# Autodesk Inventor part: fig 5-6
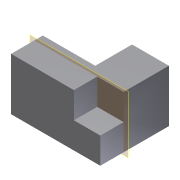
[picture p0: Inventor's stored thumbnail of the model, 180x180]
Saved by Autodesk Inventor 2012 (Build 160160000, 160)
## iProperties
Created: 2010-02
Part Number: fig 5-6
Document SubType Name: Modeling
Designer: CADSoft
Density: 1 g/cm^3
Material: Default
Author: CADSoft
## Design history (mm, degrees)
sketch "Sketch1"
  geometry: L1 (0, 26.227)-(0, 12.145); L2 (0, 12.145)-(-20.026, 12.145); L3 (-20.026, 12.145)-(-20.026, 0); L4 (-20.026, 0)-(14.083, 0); L5 (14.083, 0)-(14.083, 26.227); L6 (14.083, 26.227)-(0, 26.227); 1 further point
  constraints: 12 end point
extrude "Extrusion1" new body sketch "Sketch1" distance "d0" = 20; taper "d1" = 0 deg
sketch "Sketch2"
  geometry: L1 (14.083, 0)-(3.983, 0); L2 (3.983, 0)-(3.983, 8.922); L3 (3.983, 8.922)-(14.083, 8.922); L4 (14.083, 8.922)-(14.083, 0); 1 further point
  constraints: 8 end point
extrude "Extrusion2" cut sketch "Sketch2" distance "d2" = 10; taper "d3" = 0 deg
workplane "Work Plane1"
body "Solid1"
